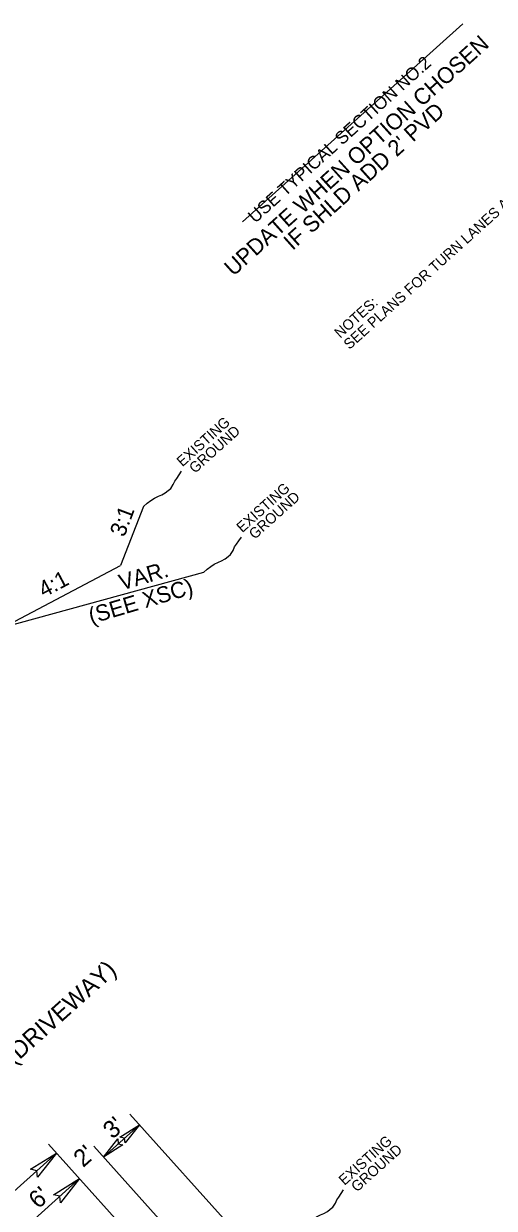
# Model space of a CAD drawing. Extents: x 2488411 to 2488707, y 383669 to 383962.
# Drawn here: x 2488468.5 to 2488497.8, y 383707.8 to 383781.4 of the extents above; entities that cross this region are included whole.
import ezdxf

# ---------------------------------------------------------------- set-up
doc = ezdxf.new("R2010")
doc.units = 0
for name, color, linetype in [('Prop Roadway Profile Bench Mark Info Text', 7, 'Continuous'), ('Sheet Data Text CELL', 7, 'Continuous'), ('Sheet Plan CELL', 7, 'Continuous'), ('Sheet Sticker Preliminary CELL', 7, 'Continuous'), ('Sheet Title CELL', 7, 'Continuous'), ('Typical Text ID Circle CELL', 7, 'Continuous')]:
    doc.layers.add(name, color=color, linetype=linetype)

msp = doc.modelspace()

# ---------------------------------------------------------------- linework, layer by layer
at = {"layer": 'Sheet Data Text CELL'}
msp.add_line((2488482.107, 383769.036), (2488495.808, 383781.353), dxfattribs=at)
at = {"layer": 'Sheet Plan CELL'}
for p, q in [((2488475.968, 383751.363), (2488474.527, 383747.702)), ((2488467.241, 383743.842), (2488474.527, 383747.702)), ((2488479.685, 383747.266), (2488467.241, 383743.842))]:
    msp.add_line(p, q, dxfattribs=at)
at = {"layer": 'Sheet Sticker Preliminary CELL'}
for points in [[(2488474.496, 383712.191), (2488475.703, 383712.951), (2488474.819, 383711.82), (2488474.785, 383712.126)], [(2488474.68, 383711.705), (2488473.472, 383710.946), (2488474.356, 383712.077), (2488474.39, 383711.771)], [(2488468.947, 383710.184), (2488470.557, 383711.197), (2488469.378, 383709.689), (2488469.333, 383710.097)], [(2488470.375, 383708.595), (2488471.985, 383709.608), (2488470.806, 383708.1), (2488470.761, 383708.508)]]:
    msp.add_lwpolyline(points, close=True, dxfattribs=at)
at = {"layer": 'Sheet Title CELL'}
for p, q in [((2488484.489, 383703.178), (2488475.103, 383713.619)), ((2488473.472, 383710.946), (2488475.703, 383712.951)), ((2488473.472, 383710.946), (2488475.703, 383712.951)), ((2488480.265, 383700.397), (2488470.053, 383711.757)), ((2488481.753, 383701.734), (2488472.872, 383711.613)), ((2488461.637, 383703.179), (2488470.557, 383711.197)), ((2488463.065, 383701.59), (2488471.985, 383709.608))]:
    msp.add_line(p, q, dxfattribs=at)
at = {"layer": 'Typical Text ID Circle CELL'}
for points in [[(2488475.968, 383751.363), (2488476.193, 383751.572), (2488476.424, 383751.733), (2488476.642, 383751.883), (2488476.896, 383751.993), (2488477.098, 383752.081), (2488477.315, 383752.205), (2488477.496, 383752.344), (2488477.652, 383752.484), (2488477.813, 383752.723), (2488477.899, 383752.942), (2488478.031, 383753.108), (2488478.167, 383753.323), (2488478.328, 383753.562)], [(2488479.685, 383747.266), (2488479.91, 383747.475), (2488480.142, 383747.636), (2488480.36, 383747.786), (2488480.613, 383747.896), (2488480.816, 383747.984), (2488481.033, 383748.108), (2488481.213, 383748.247), (2488481.369, 383748.387), (2488481.531, 383748.626), (2488481.616, 383748.845), (2488481.749, 383749.011), (2488481.884, 383749.226), (2488482.045, 383749.465)], [(2488486.037, 383706.72), (2488486.262, 383706.928), (2488486.494, 383707.089), (2488486.712, 383707.239), (2488486.965, 383707.349), (2488487.168, 383707.437), (2488487.385, 383707.561), (2488487.566, 383707.7), (2488487.722, 383707.84), (2488487.883, 383708.079), (2488487.969, 383708.298), (2488488.101, 383708.464), (2488488.236, 383708.679), (2488488.397, 383708.918)]]:
    msp.add_lwpolyline(points, dxfattribs=at)

# ---------------------------------------------------------------- texts
at = {"layer": 'Prop Roadway Profile Bench Mark Info Text'}
for s, rotation, p in [('3:1', 69.3909, (2488474.768, 383749.412)), ('VAR. ', 16.50094, (2488474.608, 383746.137)), ('4:1', 27.91758, (2488469.766, 383745.678)), ('(SEE XSC)', 16.50094, (2488472.719, 383744.052))]:
    msp.add_text(s, height=1, rotation=rotation, dxfattribs=at).set_placement(p)
at = {"layer": 'Sheet Data Text CELL'}
msp.add_text('USE TYPICAL SECTION NO.2', height=0.8, rotation=41.95382, dxfattribs=at).set_placement((2488482.9, 383768.92))
at = {"layer": 'Sheet Sticker Preliminary CELL'}
for s, p in [('UPDATE WHEN OPTION CHOSEN', (2488481.541, 383765.623)), ("IF SHLD ADD 2' PVD", (2488485.223, 383767.228))]:
    msp.add_text(s, height=1, rotation=41.95382, dxfattribs=at).set_placement(p)
at = {"layer": 'Sheet Title CELL'}
for s, height, p in [('SEE PLANS FOR TURN LANES AND TAPER.', 0.65, (2488488.756, 383761.078)), ('NOTES:', 0.65, (2488488.181, 383761.782)), ('EXISTING', 0.65, (2488478.38, 383753.798)), ('GROUND', 0.65, (2488479.152, 383753.384)), ('EXISTING', 0.65, (2488482.098, 383749.701)), ('GROUND', 0.65, (2488482.869, 383749.287)), ('-DRV- (DRIVEWAY)', 1.0817, (2488464.613, 383713.691)), ("3'", 1.0817, (2488474.042, 383712.02)), ("2'", 1.0817, (2488472.21, 383710.259)), ('EXISTING', 0.65, (2488488.45, 383709.154)), ('GROUND', 0.65, (2488489.222, 383708.74)), ("6'", 1.0817, (2488469.421, 383707.684))]:
    msp.add_text(s, height=height, rotation=41.95382, dxfattribs=at).set_placement(p)

doc.saveas('drawing.dxf')
